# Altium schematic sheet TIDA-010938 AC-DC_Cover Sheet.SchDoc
size 431 x 279 mm; Date: Not shown in title block; ApprovedBy: Not shown in title block; CheckedBy: Not shown in title block; Author: Not shown in title block; CompanyName: Not shown in title block; Engineer: Not shown in title block; Organization: Not shown in title block; Address1: Not shown in title block; Address2: Not shown in title block; Address3: Not shown in title block; Address4: Not shown in title block; DocumentNumber: 8; Revision: Use project parameter SCH_Rev; SheetNumber: 2; SheetTotal: 11; PageSetup: Record=PageOptions¦CenterHorizontal=True¦CenterVertical=True¦PrintScale=1.00¦XCorrection=1.00¦YCorrection=1.00¦PrintKind=0¦BorderSize=5000000¦LeftOffset=0¦BottomOffset=0¦Orientation=2¦PaperLength=1000¦PaperWidth=1000¦Scale=100¦PaperSource=15¦PrintQuality=600¦MediaType=1¦DitherType=10¦PaperKind=Letter¦PrintScaleMode=1
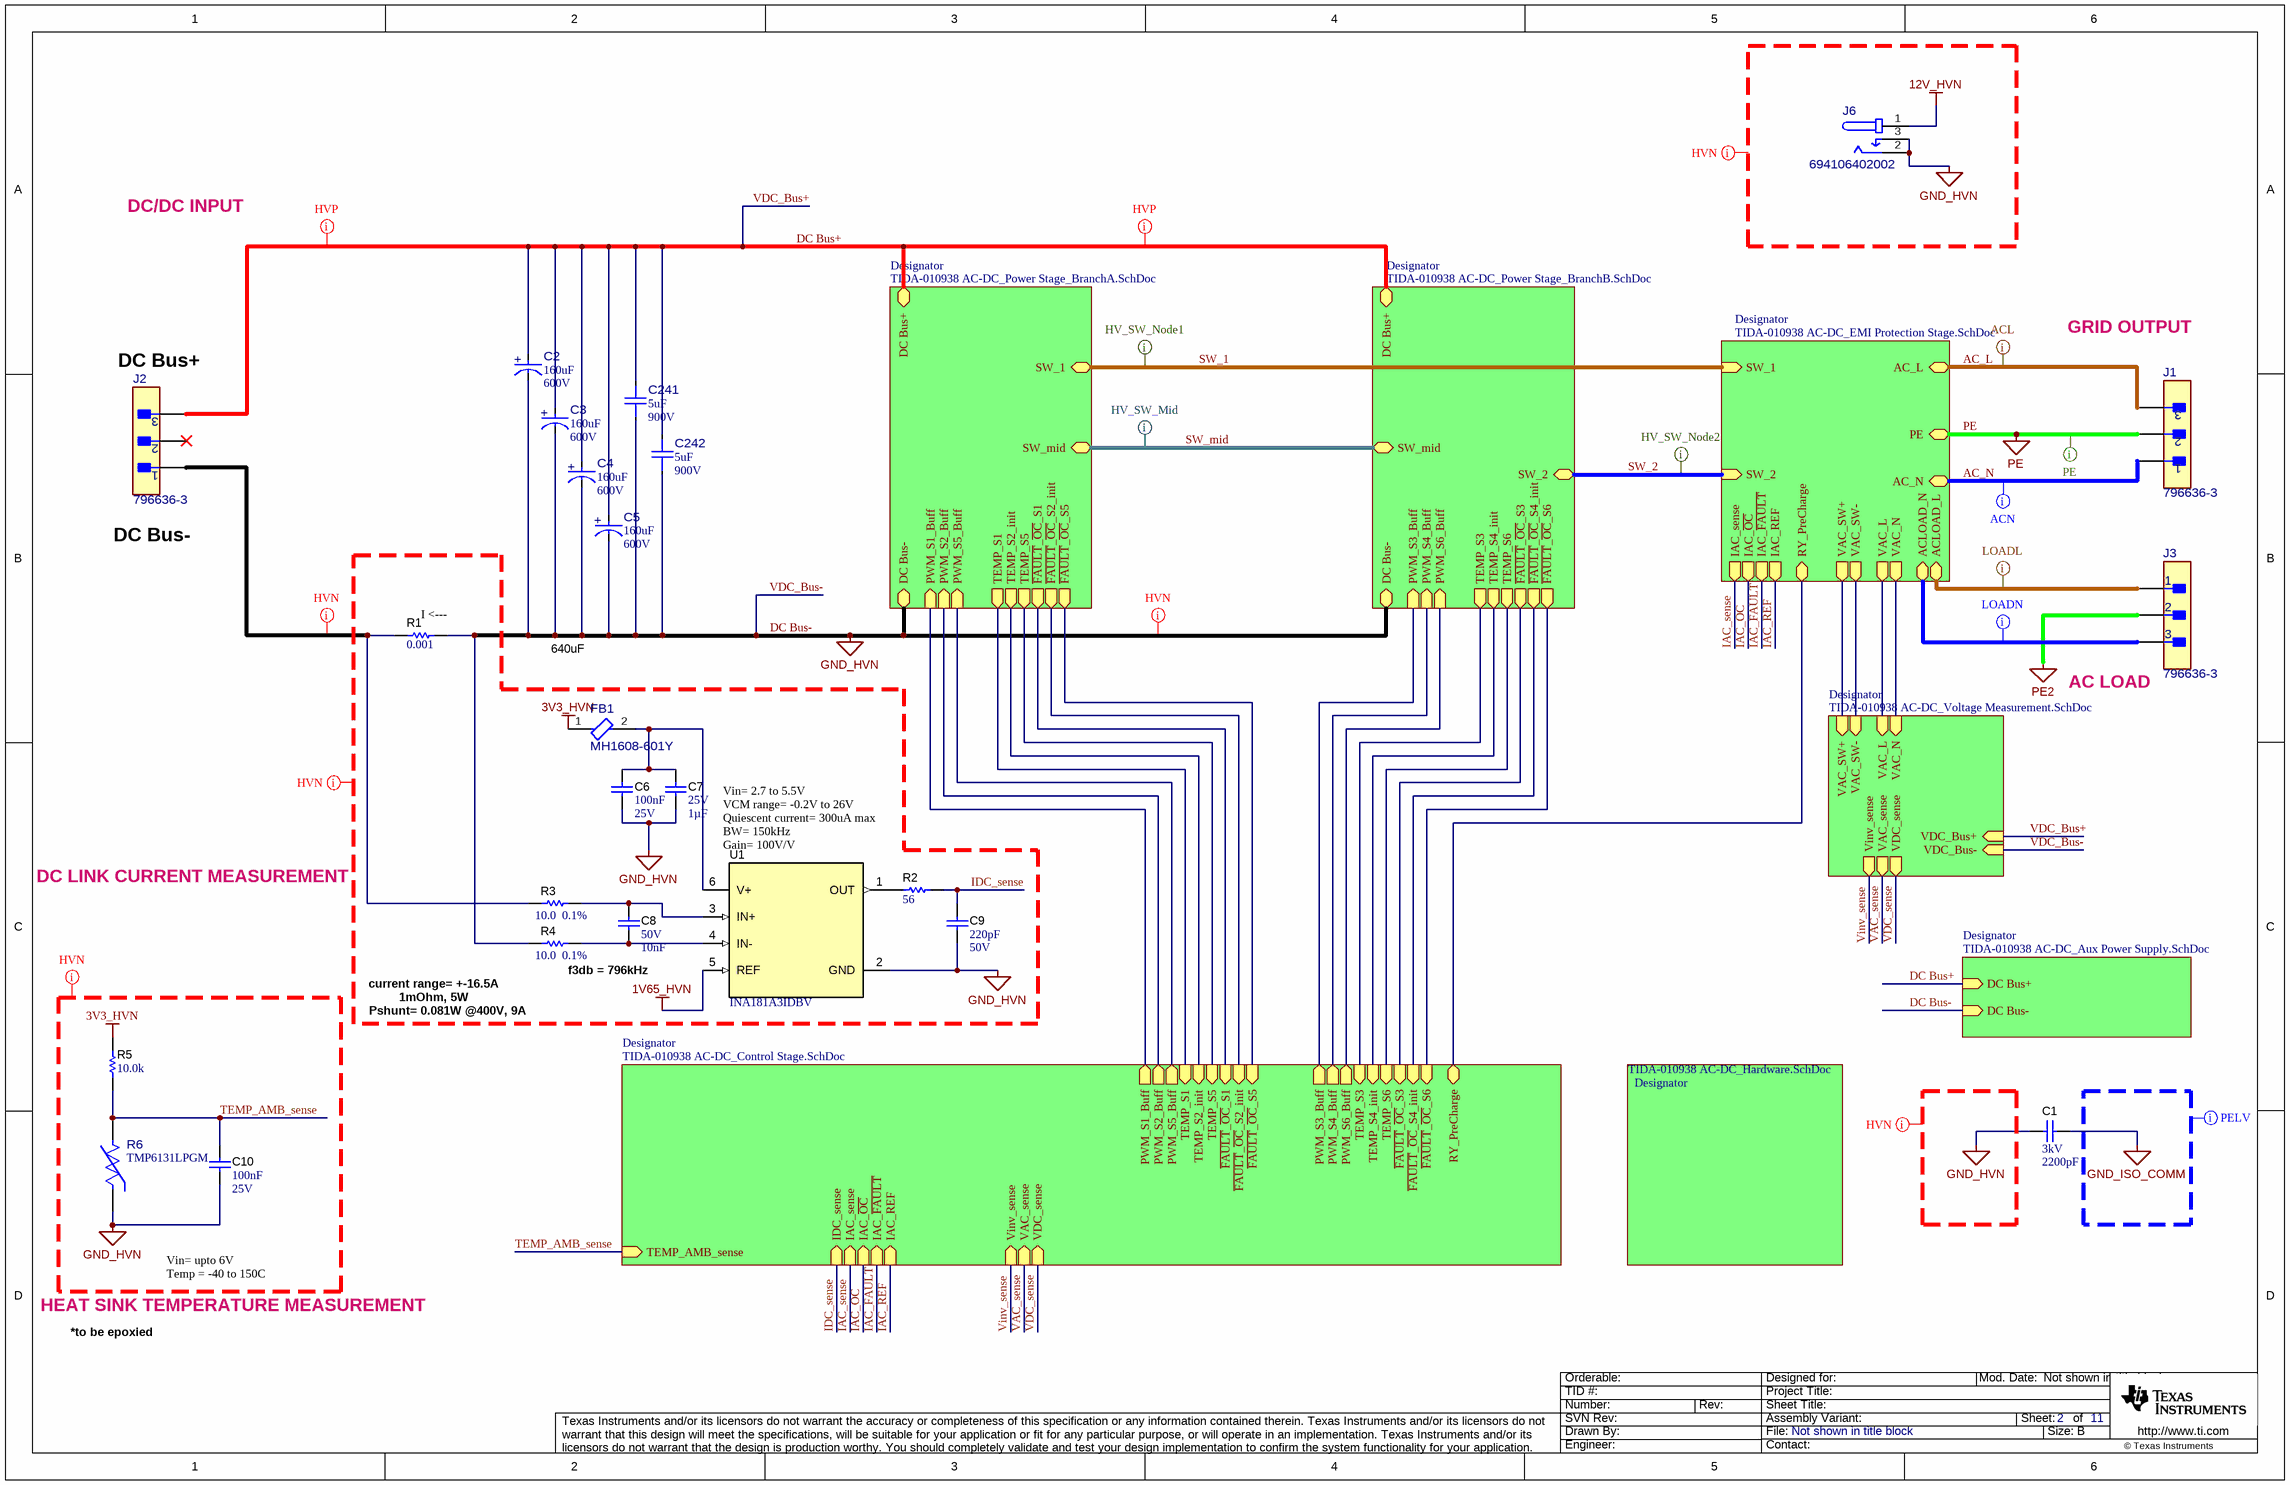
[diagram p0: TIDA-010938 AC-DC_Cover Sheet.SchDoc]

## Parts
C1  VDC_V: 3kV  ValueDisplayed: 2200pF  [CK45_1250x600x1650]  (hidden comment: CK45-B3FD222KYVNA)
C2  ValueDisplayed: 160uF  VDC_V: 600V  [FP-ALH82D161DD600_RADIAL-MFG]  (hidden comment: ALH82D161DD600)
C3  ValueDisplayed: 160uF  VDC_V: 600V  [FP-ALH82D161DD600_RADIAL-MFG]  (hidden comment: ALH82D161DD600)
C4  ValueDisplayed: 160uF  VDC_V: 600V  [FP-ALH82D161DD600_RADIAL-MFG]  (hidden comment: ALH82D161DD600)
C5  ValueDisplayed: 160uF  VDC_V: 600V  [FP-ALH82D161DD600_RADIAL-MFG]  (hidden comment: ALH82D161DD600)
C6  Cap_F: 100nF  VDC_V: 25V  [0603]  (hidden comment: 06033C104JAT2A)
C7  VDC_V: 25V  ValueDisplayed: 1µF  [0603]  (hidden comment: TMK107BJ105KA-T)
C8  VDC_V: 50V  Cap_F: 10nF  [0603]  (hidden comment: 885012206089)
C9  Cap_F: 220pF  VDC_V: 50V  [0603]  (hidden comment: GRM188R71H221KA01D)
C10  Cap_F: 100nF  VDC_V: 25V  [0603]  (hidden comment: 06033C104JAT2A)
C241  ValueDisplayed: 5uF  VDC_V: 900V  [FP-C4AKOBU4500A31J_RADIAL-MFG]  (hidden comment: C4AKOBU4500A31J)
C242  ValueDisplayed: 5uF  VDC_V: 900V  [FP-C4AKOBU4500A31J_RADIAL-MFG]  (hidden comment: C4AKOBU4500A31J)
FB1  MH1608-601Y  [FP-MH1608-601Y_0603-MFG]
J1  796636-3  [FP-796636-3_HDR3-MFG]
J2  796636-3  [FP-796636-3_HDR3-MFG]
J3  796636-3  [FP-796636-3_HDR3-MFG]
J6  694106402002  [FP-694106402002_CONN_PWR_10MM7_9MM0-MFG]
R1  ValueDisplayed: 0.001  [CSS2H-2512_H077Y042]  (hidden comment: CSS2H-2512R-1L00F)
R2  ValueDisplayed: 56  [0603]  (hidden comment: RG1608P-560-B-T5)
R3  Tolerance_%: 0.1%  ValueDisplayed: 10.0  [0603]  (hidden comment: RT0603BRD0710RL)
R4  Tolerance_%: 0.1%  ValueDisplayed: 10.0  [0603]  (hidden comment: RT0603BRD0710RL)
R5  ValueDisplayed: 10.0k  [0603]  (hidden comment: RG1608P-103-B-T5)
R6  TMP6131LPGM  [LPG0002A-MFG]
U1  INA181A3IDBV  [DBV0006A_N]

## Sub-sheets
Designator = TIDA-010938 AC-DC_Power Stage_BranchA.SchDoc: TEMP_S5 (out), TEMP_S1 (out), DC Bus+ (bidir), SW_mid (bidir), SW_1 (bidir), DC Bus- (bidir), PWM_S1_Buff (in), PWM_S5_Buff (in), PWM_S2_Buff (in), TEMP_S2_init (out), ~{FAULT}_~{OC}_S5 (out), ~{FAULT}_~{OC}_S1 (out), ~{FAULT}_~{OC}_S2_init (out)
Designator = TIDA-010938 AC-DC_Power Stage_BranchB.SchDoc: TEMP_S6 (out), TEMP_S3 (out), DC Bus+ (bidir), SW_mid (bidir), SW_2 (bidir), DC Bus- (bidir), PWM_S6_Buff (in), PWM_S3_Buff (in), PWM_S4_Buff (in), TEMP_S4_init (out), ~{FAULT}_~{OC}_S6 (out), ~{FAULT}_~{OC}_S3 (out), ~{FAULT}_~{OC}_S4_init (out)
Designator = TIDA-010938 AC-DC_EMI Protection Stage.SchDoc: AC_L (bidir), AC_N (bidir), SW_1 (in), SW_2 (in), VAC_SW+ (out), VAC_SW- (out), VAC_L (out), VAC_N (out), IAC_sense (out), IAC_~{OC} (out), IAC_~{FAULT} (out), IAC_REF (out), RY_PreCharge (bidir), PE (bidir), ACLOAD_L (bidir), ACLOAD_N (bidir)
Designator = TIDA-010938 AC-DC_Voltage Measurement.SchDoc: VDC_sense (out), Vinv_sense (out), VAC_N (in), VAC_L (in), VAC_SW- (in), VAC_SW+ (in), VAC_sense (out), VDC_Bus+ (in), VDC_Bus- (in)
Designator = TIDA-010938 AC-DC_Control Stage.SchDoc: IAC_REF (in), IAC_sense (in), VAC_sense (in), Vinv_sense (in), VDC_sense (in), IDC_sense (in), TEMP_AMB_sense (in), PWM_S1_Buff (out), PWM_S2_Buff (out), PWM_S3_Buff (out), PWM_S4_Buff (out), PWM_S5_Buff (out), PWM_S6_Buff (out), TEMP_S2_init (in), TEMP_S4_init (in), RY_PreCharge (bidir), IAC_~{FAULT} (in), IAC_~{OC} (in), TEMP_S1 (in), TEMP_S3 (in), TEMP_S5 (in), TEMP_S6 (in), ~{FAULT}_~{OC}_S5 (in), ~{FAULT}_~{OC}_S6 (in), ~{FAULT}_~{OC}_S1 (in), ~{FAULT}_~{OC}_S3 (in), ~{FAULT}_~{OC}_S2_init (in), ~{FAULT}_~{OC}_S4_init (in)
Designator = TIDA-010938 AC-DC_Hardware.SchDoc: no entries
Designator = TIDA-010938 AC-DC_Aux Power Supply.SchDoc: DC Bus+ (in), DC Bus- (in)

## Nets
1V65_HVN: U1.5(REF)
3V3_HVN: FB1.1 R5.2
12V_HVN: J6.1
DC Bus-: C1.2 C2.1(CATHODE) C3.1(CATHODE) C4.1(CATHODE) C5.1(CATHODE) C6.2 C7.2 C9.1 C10.2 C241.1 C242.1 J6.2 J6.3 R1.2 R4.1 R6.2(+) U1.2(GND) ; sheet Designator/DC Bus-, sheet Designator/DC Bus-, sheet Designator/VDC_Bus-, sheet Designator/DC Bus-  [also labelled GND_HVN, VDC_Bus-]
GND_ISO_COMM: C1.1
PE: J1.2 ; sheet Designator/PE
PE2: J3.2
AC_L: J1.3 ; sheet Designator/AC_L
AC_N: J1.1 ; sheet Designator/AC_N
DC Bus+: C2.2(ANODE) C3.2(ANODE) C4.2(ANODE) C5.2(ANODE) C241.2 C242.2 J2.3 ; sheet Designator/DC Bus+, sheet Designator/DC Bus+, sheet Designator/VDC_Bus+, sheet Designator/DC Bus+  [also labelled VDC_Bus+]
IAC_~{FAULT}: sheet Designator/IAC_~{FAULT}, sheet Designator/IAC_~{FAULT}
IAC_~{OC}: sheet Designator/IAC_~{OC}, sheet Designator/IAC_~{OC}
IAC_REF: sheet Designator/IAC_REF, sheet Designator/IAC_REF
IAC_sense: sheet Designator/IAC_sense, sheet Designator/IAC_sense
IDC_sense: C9.2 R2.2 ; sheet Designator/IDC_sense
SW_1: sheet Designator/SW_1, sheet Designator/SW_1
SW_2: sheet Designator/SW_2, sheet Designator/SW_2
SW_mid: sheet Designator/SW_mid, sheet Designator/SW_mid
TEMP_AMB_sense: C10.1 R5.1 R6.1(-) ; sheet Designator/TEMP_AMB_sense
VAC_sense: sheet Designator/VAC_sense, sheet Designator/VAC_sense
VDC_sense: sheet Designator/VDC_sense, sheet Designator/VDC_sense
Vinv_sense: sheet Designator/Vinv_sense, sheet Designator/Vinv_sense
NetC6_1: C6.1 C7.1 FB1.2 U1.6(V+)
NetC8_1: C8.1 R3.2 U1.3(IN+)
NetC8_2: C8.2 R4.2 U1.4(IN-)
NetJ2_1: J2.1 R1.1 R3.1
NetJ3_1: J3.1 ; sheet Designator/ACLOAD_L
NetJ3_3: J3.3 ; sheet Designator/ACLOAD_N
NetR2_1: R2.1 U1.1(OUT)
(unnamed): sheet Designator/TEMP_S5, sheet Designator/TEMP_S5
(unnamed): sheet Designator/TEMP_S1, sheet Designator/TEMP_S1  [a separate net that carries the same name]
(unnamed): sheet Designator/PWM_S1_Buff, sheet Designator/PWM_S1_Buff  [a separate net that carries the same name]
(unnamed): sheet Designator/PWM_S5_Buff, sheet Designator/PWM_S5_Buff  [a separate net that carries the same name]
(unnamed): sheet Designator/PWM_S2_Buff, sheet Designator/PWM_S2_Buff  [a separate net that carries the same name]
(unnamed): sheet Designator/TEMP_S2_init, sheet Designator/TEMP_S2_init  [a separate net that carries the same name]
(unnamed): sheet Designator/~{FAULT}_~{OC}_S5, sheet Designator/~{FAULT}_~{OC}_S5  [a separate net that carries the same name]
(unnamed): sheet Designator/~{FAULT}_~{OC}_S1, sheet Designator/~{FAULT}_~{OC}_S1  [a separate net that carries the same name]
(unnamed): sheet Designator/~{FAULT}_~{OC}_S2_init, sheet Designator/~{FAULT}_~{OC}_S2_init  [a separate net that carries the same name]
(unnamed): sheet Designator/TEMP_S6, sheet Designator/TEMP_S6  [a separate net that carries the same name]
(unnamed): sheet Designator/TEMP_S3, sheet Designator/TEMP_S3  [a separate net that carries the same name]
(unnamed): sheet Designator/PWM_S6_Buff, sheet Designator/PWM_S6_Buff  [a separate net that carries the same name]
(unnamed): sheet Designator/PWM_S3_Buff, sheet Designator/PWM_S3_Buff  [a separate net that carries the same name]
(unnamed): sheet Designator/PWM_S4_Buff, sheet Designator/PWM_S4_Buff  [a separate net that carries the same name]
(unnamed): sheet Designator/TEMP_S4_init, sheet Designator/TEMP_S4_init  [a separate net that carries the same name]
(unnamed): sheet Designator/~{FAULT}_~{OC}_S6, sheet Designator/~{FAULT}_~{OC}_S6  [a separate net that carries the same name]
(unnamed): sheet Designator/~{FAULT}_~{OC}_S3, sheet Designator/~{FAULT}_~{OC}_S3  [a separate net that carries the same name]
(unnamed): sheet Designator/~{FAULT}_~{OC}_S4_init, sheet Designator/~{FAULT}_~{OC}_S4_init  [a separate net that carries the same name]
(unnamed): sheet Designator/VAC_SW+, sheet Designator/VAC_SW+  [a separate net that carries the same name]
(unnamed): sheet Designator/VAC_SW-, sheet Designator/VAC_SW-  [a separate net that carries the same name]
(unnamed): sheet Designator/VAC_L, sheet Designator/VAC_L  [a separate net that carries the same name]
(unnamed): sheet Designator/VAC_N, sheet Designator/VAC_N  [a separate net that carries the same name]
(unnamed): sheet Designator/RY_PreCharge, sheet Designator/RY_PreCharge  [a separate net that carries the same name]

Not connected (* = marked no-connect by the designer): J2 2*

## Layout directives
net class HVN: 1V65_HVN, 3V3_HVN, 12V_HVN, DC Bus-, GND_HVN, IDC_sense, NetJ2_1, TEMP_AMB_sense, VDC_Bus-
net class HVP: DC Bus+
net class PELV: GND_ISO_COMM
net class ACL: AC_L
net class ACN: AC_N
net class PE: PE
net class HV_SW_Node1: SW_1
net class HV_SW_Mid: SW_mid
net class HV_SW_Node2: SW_2
net class LOADL: NetJ3_1
net class LOADN: NetJ3_3

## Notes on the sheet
- DC/DC INPUT
- (near J2) DC Bus+
- GRID OUTPUT
- DC Bus-
- (near R1) I <---
- 640uF
- (near J3) AC LOAD
- DC LINK CURRENT MEASUREMENT
- Vin= 2.7 to 5.5V
  VCM range= -0.2V to 26V
  Quiescent current= 300uA max
  BW= 150kHz
  Gain= 100V/V
- f3db = 796kHz
- (near R4) current range= +-16.5A
- 1mOhm, 5W
- Pshunt= 0.081W @400V, 9A
- Vin= upto 6V
  Temp = -40 to 150C
- HEAT SINK TEMPERATURE MEASUREMENT
- *to be epoxied

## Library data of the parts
C1 = CMP-0086078-1: CAP, CERM, 2200 pF, 3000 V,+/- 10%, B, Dia 12.5mm; Manufacturer: TDK; AEC Qualified: N; SizeAreaWB_mm2: 116; Cap_Case: 12.5x6x16.5mm; SizeZ_mm: 16.5; AEC Category: Q200; TaMin_C: -25°C; SizeX_mm: 12.5; SizeY_mm: 6; Value2: 3000V; TaMax_C: 105°C; Value: 2200pF; SizeArea_mm2: 75; U/M: EA; Cap_F: 2.2nF
C2-C5 = CMP-0033686-1: ALH82, Aluminum Electrolytic, 160 uF, 20%, 600 VDC, -40/+105°C; Manufacturer: KEMET; AEC Qualified: No; Cap_F: 160µF; IRMS_A: 4.51A; SizeZ_mm: 42mm; Esr: 0.877; Leakage Current: 288uA; Life: 3000Hours; Value: 160µF
C6 C10 = CMP-0006752-5: CAP, CERM, 0.1 uF, 25 V, +/- 5%, X7R, 0603; Manufacturer: AVX; TaMin_C: -55°C; ESR_ohm: 0.05; Polarized: N; SizeAreaWB_mm2: 4.68; Value1: 0.05 ohm; U/M: EA; Value: 0.1uF; TaMax_C: 125°C; SizeZ_mm: 1; SizeX_mm: 1.6; SizeY_mm: 0.8; SizeArea_mm2: 1.28; AEC Category: Q200
C7 = CMP-0086152-1: CAP, CERM, 1 µF, 25 V,+/- 10%, X5R, 0603; Manufacturer: Taiyo Yuden; SizeAreaWB_mm2: 4.68; SizeZ_mm: 1; U/M: EA; Green_REACh: Passed; Value: 1uF; AEC Qualified: N; TaMax_C: 85°C; Green_Lifecycle: Active; AEC Category: Q200; SizeArea_mm2: 1.28; TaMin_C: -55°C; SizeY_mm: 0.8; SizeX_mm: 1.6
C8 = CMP-0750039-1: CAP, CERM, 0.01 µF, 50 V,+/- 10%, X7R, 0603; Manufacturer: Wurth Elektronik; Polarized: N; AEC Category: Q200; TaMax_C: 125°C; SizeAreaWB_mm2: 4.68; Value: 0.01uF; SizeArea_mm2: 1.28; SizeY_mm: 0.8; SizeZ_mm: 1; ValueDisplayed: 0.01µF; SizeX_mm: 1.6; U/M: EA; TaMin_C: -55°C
C9 = CMP-0007442-5: CAP, CERM, 220 pF, 50 V, +/- 10%, X7R, 0603; Manufacturer: MuRata; TaMin_C: -55°C; Polarized: N; SizeAreaWB_mm2: 4.68; Value1: Unknown; U/M: EA; Value: 220pF; TaMax_C: 125°C; SizeZ_mm: 1; SizeX_mm: 1.6; SizeY_mm: 0.8; SizeArea_mm2: 1.28; AEC Category: Q200
C241 C242 = CMP-0037193-1: 5 µF Film Capacitor 900V Polypropylene (PP), Metallized Radial; Manufacturer: Kemet; AEC Grade: Grade 1; AEC Qualified: No; Cap_F: 5µF; SizeZ_mm: 29.7mm; Tolerance_%: 5%; Standoff Height: 0.5mm; Value: 5µF
FB1 = CMP-0037505-1: 600 Ohms @ 100 MHz 1 Power, Signal Line Ferrite Bead 0603 (1608 Metric) 1A 200mOhm; Manufacturer: Bourns; DCR_ohm: 0.2; SizeZ_mm: 1mm; AEC Qualified: No; Impedance At Frequency: 600Ω @ 100MHz; Test Frequency: 100MHz; Tolerance_%: 25%
J1-J3 = CMP-0094328-1: 3 Position Terminal Block Header, Male Pins, Shrouded (4 Side) 0.200" (5.08mm) Vertical - Through Hole; Manufacturer: TE Connectivity; Current_A: 15A; Row_Count: 1; AEC Qualified: No; Voltage_V: 300V; SizeZ_mm: 12.25mm; Min Wire Gauge: 30; ContactFinish: Tin; Max Wire Gauge: 12
J6 = CMP-0040211-1: Power Barrel Connector Jack 2.10mm ID (0.083"), 5.50mm OD (0.217") Through Hole; Manufacturer: Wurth Electronics; ContactFinish: Gold; Current_A: 3A; Voltage_V: 30V; AEC Qualified: No; Conn Gender: Female; Conn Orientation: Vertical; SizeZ_mm: 14.3mm
R1 = CMP-0084746-1: RES, 0.001, 1%, 5 W, AEC-Q200 Grade 0, 6.35x3.05mm; Manufacturer: Bourns; SizeAreaWB_mm2: 42.1675; SizeArea_mm2: 19.3675; SizeY_mm: 3.05; SizeX_mm: 6.35; AEC Grade: 0; EIA_Code: E96; Value: 0.001; Res_ohm: 1m; Power_W: 5W; SizeZ_mm: 0.87; TempCo: 75 ppm/C; Value_Code: 1L000; AEC Qualified: Y; AEC Category: Q200
R2 = CMP-0023572-3: RES, 56, 0.1%, 0.1 W, 0603; Manufacturer: Susumu Co Ltd; Power_W: 100mW; TempCo: 25 ppm/C; Value_Code: 56R0; U/M: EA; Value: 56; SizeX_mm: 1.6; SizeY_mm: 0.8; SizeZ_mm: 1; Value2: 0.1W; SizeArea_mm2: 1.28; VDC_V: 75V; AEC Category: Q200
R3 R4 = CMP-0023661-3: RES, 10.0, 0.1%, 0.1 W, 0603; Manufacturer: Yageo America; Power_W: 100mW; TempCo: 25 ppm/C; Value_Code: 10R0; U/M: EA; Value: 10.0; EIA_Code: E192; Res_ohm: 10; SizeX_mm: 1.6; SizeY_mm: 0.8; SizeZ_mm: 1; Value2: 0.1W; SizeArea_mm2: 1.28; VDC_V: 75V; AEC Category: Q200
R5 = CMP-0023404-3: RES, 10.0 k, 0.1%, 0.1 W, 0603; Manufacturer: Susumu Co Ltd; Power_W: 100mW; TempCo: 25 ppm/C; Value_Code: 10k0; U/M: EA; Value: 10.0k; EIA_Code: E192; Res_ohm: 10k; SizeX_mm: 1.6; SizeY_mm: 0.8; SizeZ_mm: 1; Value2: 0.1W; SizeArea_mm2: 1.28; VDC_V: 75V; AEC Category: Q200
R6 = CMP-0089579-1: SENSOR PTC 10K OHM 1% TO92S; Manufacturer: Texas Instruments; TJmax_C: +155°C; AEC Qualified: No; Value: 10kΩ; SizeZ_mm: 5.05mm; Max Current: 400uA; TaMax_C: +150°C; TempCo: 6400ppm/°C; TaMin_C: -40°C; VDC_V: 5.5V
U1 = CMP-0013234-2: Bidirectional, Low- and High-Side Measurement, Multichannel, Voltage Output, Current-Sense Amplifier, DBV0006A (SOT-6); Manufacturer: Texas Instruments; SizeX_mm: 2.8; SizeY_mm: 2.9; CompType: IC; SizeZ_mm: 1.45; SizeArea_mm2: 8.12; SizeAreaWB_mm2: 14.82; U/M: EA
